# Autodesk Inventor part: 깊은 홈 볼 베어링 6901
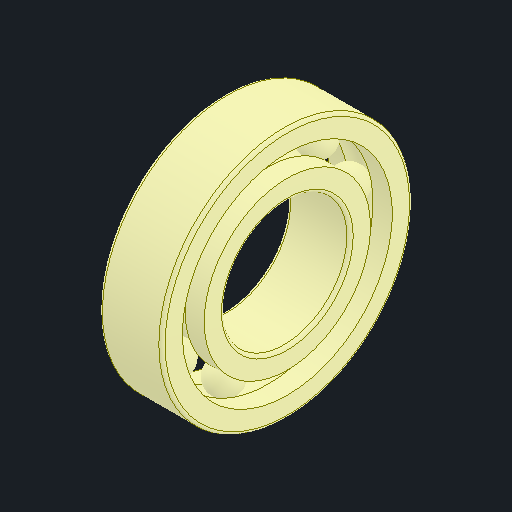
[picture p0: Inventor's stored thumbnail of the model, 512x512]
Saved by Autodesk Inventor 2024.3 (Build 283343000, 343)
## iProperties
Created: 2024-05
Part Number: 깊은 홈 볼 베어링 6901
Material: 강철, 연강
Description: 깊은 그루브 볼 베어링
Document SubType Name: Modeling
Designer: MyPc
Density: 7.85 g/cm^3
Appearance: 기본값
Author: jhkim
Sending System: Autodesk Inventor 2025
Preprocessor: ST-DEVELOPER v20
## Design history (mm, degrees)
node "깊은 홈 볼 베어링 69011"
node "솔리드1"
node "솔리드2"
node "솔리드3"
node "솔리드4"
node "솔리드5"
node "솔리드6"
node "솔리드7"
node "솔리드8"
node "솔리드9"
node "솔리드10"
node "솔리드11"
body "Solid1"
node "Solid1:1"
node "Solid1:2"
node "Solid1:3"
node "Solid1:4"
node "Solid1:5"
node "Solid1:6"
node "Solid1:7"
node "Solid1:8"
node "Solid1:9"
node "Solid1:10"
